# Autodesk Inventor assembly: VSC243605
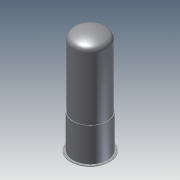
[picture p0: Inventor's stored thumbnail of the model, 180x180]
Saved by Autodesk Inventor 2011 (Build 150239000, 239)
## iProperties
Created: 2010-06
Part Number: VSC243605
Document SubType Name: Assembly
Designer: mklassen
OD: 36.000 in
THK: 0.625 in
LEN: 6.000 ft
SKLEN: 3.000 ft
SKOFS: 6.000 in
Author: mklassen
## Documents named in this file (3)
- O:\cadd\tutorials\inventor 2011\iLogic\VSC243605.iam
- O:\cadd\tutorials\inventor 2011\iLogic\VS243605-01.iam
- O:\cadd\tutorials\inventor 2011\iLogic\VSK243605-03.iam
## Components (2 placed, 2 different names)
1. VS243605-01:1 [sub-assembly] — Mate:1, Flush:2
2. VSK243605-03:1 [sub-assembly] — Flush:3, Flush:4
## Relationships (4: Flush 3, Mate 1)
- Mate:1: VS243605-01:1
- Flush:2: VS243605-01:1
- Flush:3: VSK243605-03:1
- Flush:4: VSK243605-03:1
## Named parameters: SKOFS = 152.4 mm, SKLEN = 914.4 mm
